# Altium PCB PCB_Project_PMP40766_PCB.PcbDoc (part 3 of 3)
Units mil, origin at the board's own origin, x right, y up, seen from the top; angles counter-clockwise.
Board outline 7480.31 x 3937.01 mil, 2 copper layers (Top Layer, Bottom Layer), stack 64.8 mil thick; 214 components, 118 nets, 518 pads, 70 vias.
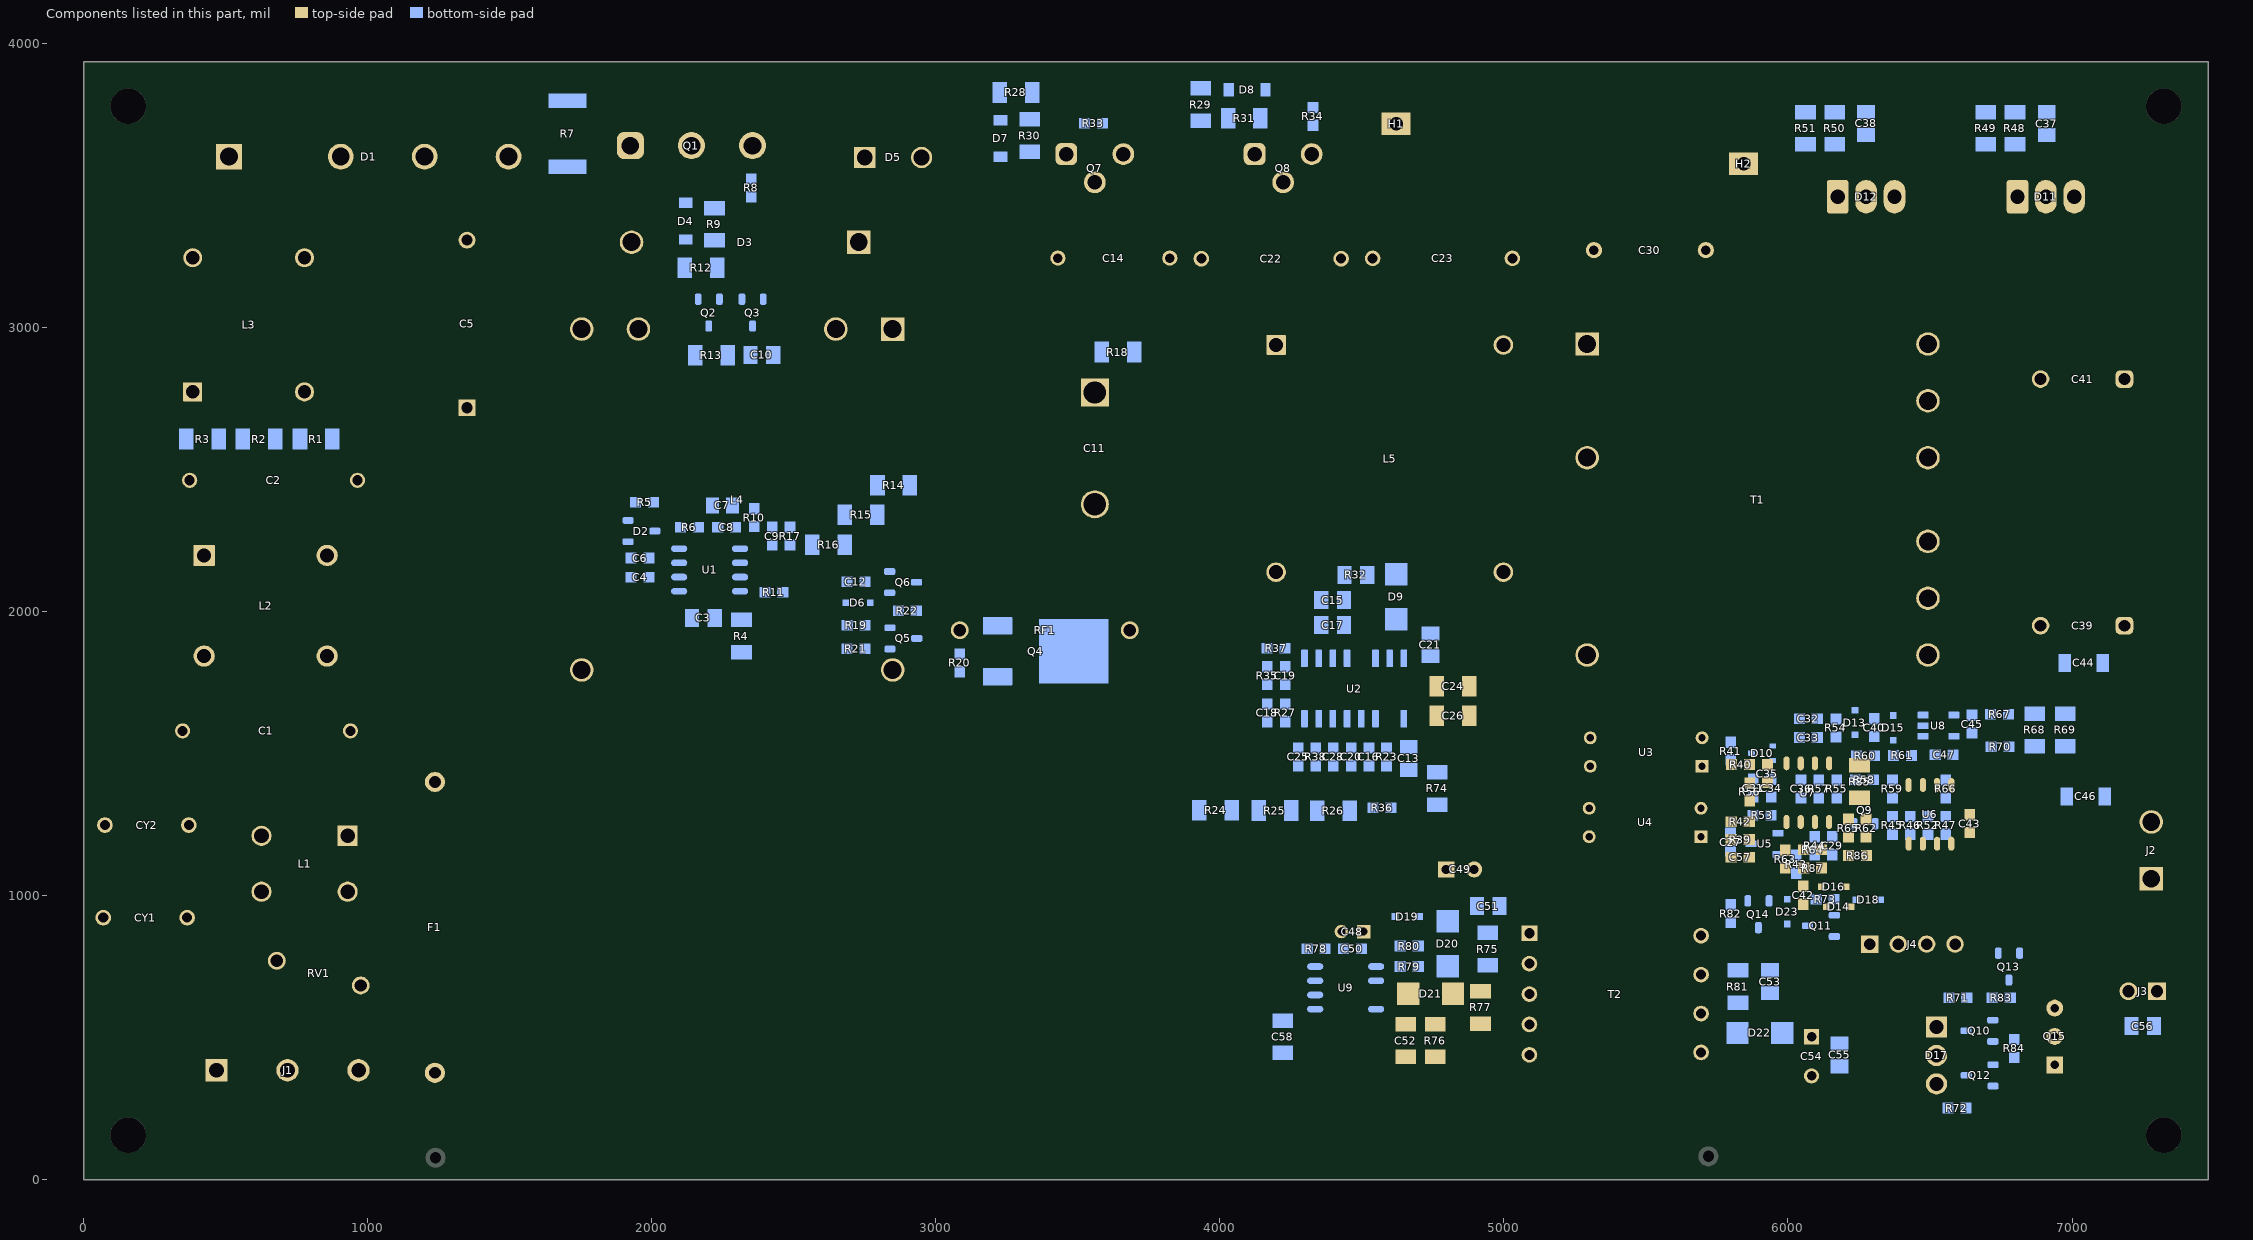
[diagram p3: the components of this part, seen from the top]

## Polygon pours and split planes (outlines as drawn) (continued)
NetC52_2 on Top Layer "Top Layer-No Net 17" (solid, pour order 136): 4623,696.26 4702,696.26 4704,694.26 4704,588.26 4717,575.26 4794,575.26 4798,571.26 4798,523.26 4795,520.26 4619,520.26 4616,523.26 4616,689.26
VBUS on Top Layer "Top Layer-No Net 18" (solid, pour order 138): 4616,471.26 5105,471.26 5118,458.26 5118,418.26 5105,405.26 4617,405.26 4610,412.26 4610,465.26
PGND on Top Layer "Top Layer-No Net 19" (solid, pour order 154): 5128,840.26 5105,817.26 5004,817.26 4944,757.26 4548,757.26 4493,702.26 4493,593.26 4447,547.26 3989,547.26 3811,725.26 3811,1409.26 4215,1813.26 4441,1813.26 4467,1787.26 4467,1767.26 4279,1579.26 4279,1542.26 4297.26,1524 4473.26,1524 4512,1485.26 4512,1337.26 4528,1321.26 4572,1321.26 4591,1340.26 4591,1450.26 4613,1472.26 4675,1472.26 4726,1421.26 4995,1421.26 5128,1288.26 5128,860.26
NetC42_2 on Top Layer "Top Layer-No Net 22" (solid, pour order 206): 6036,947 6031,952 6031,990 6035,994 6083,994 6089,1000 6089,1061 6094,1066 6139,1066 6144,1061 6144,985 6154,975 6154,952 6149,947
SGND on Bottom Layer "Bottom Layer-No Net 58" (solid, remove dead copper, pour order 214): 5753.65,1663.98 6696.65,1663.98 6800.65,1559.98 6800.65,1058.98 6921.65,937.98 7338.65,937.98 7449.65,826.98 7449.65,550.98 7450.65,549.98 7450.65,404.98 7079.39,33.72 5698.65,33.72 5665.65,66.72 5665.65,1572.72
NetF1_1 on Bottom Layer "Top Layer-No Net 1" (solid, remove dead copper, pour order 194): 858.5,932.5 913.5,877.5 913.5,620.5 946.5,587.5 1037.5,587.5 1068.5,618.5 1068.5,826.5 1161.5,919.5 1293.5,1051.5 1293.5,1411.5 1264,1441 1174,1441 1142.5,1409.5 1142.5,1144.24 1067.5,1069.24 898.5,1069.24 858.5,1029.24
"N Wire" on Bottom Layer "Top Layer-No Net 2" (solid, pour order 192): 673,321 645,349 645,605.26 539,711.26 539,1001.26 595.74,1058 683,1058 724,1017 724,899.26 802,821.26 802,349 774,321
EARTH on Bottom Layer "Bottom Layer-No Net 4" (solid, pour order 188): 22,1330.26 116,1330.26 133,1313.26 133,650 331.74,451.26 485.74,451.26 510,427 510,228 610,128 1268,128 1297,99 1297,37 1276,16 469,16 362,123 362,233 244,351 104.26,351 4,451.26 4,1312.26
12VS on Bottom Layer "Bottom Layer-No Net 57" (solid, pour order 182): 5772,927.26 5885,927.26 5941,871.26 6049,871.26 6110,810.26 6110,577.26 6004,683.26 6004,764.26 5975,793.26 5783,793.26 5748,828.26 5748,903.26
NetD7_1 on Bottom Layer "Bottom Layer-No Net 56" (solid, pour order 180): 3255,3869.26 3208,3869.26 3200,3861.26 3200,3709.26 3210,3699.26 3248,3699.26 3260,3711.26 3260,3864.26
PGND on Bottom Layer "Bottom Layer-No Net 55" (solid, pour order 178): 4355,3734.26 4308,3734.26 4284,3710.26 4284,3584.26 4300,3568.26 4346,3568.26 4364,3586.26 4364,3725.26
NetD8_2 on Bottom Layer "Bottom Layer-No Net 54" (solid, remove dead copper, pour order 176): 4305,3751.26 4201,3751.26 4174,3724.26 4174,3700.26 4161,3687.26 4161,3584.26 4145,3568.26 4092,3568.26 4076,3584.26 4076,3853.26 4095,3872.26 4330,3872.26 4352,3850.26 4352,3756.26 4347,3751.26
NetD8_1 on Bottom Layer "Bottom Layer-No Net 53" (solid, remove dead copper, pour order 174): 3897,3873.26 3891,3867.26 3891,3811.26 3896,3806.26 4048,3806.26 4057,3815.26 4057,3866.26 4050,3873.26
12VS on Bottom Layer "Bottom Layer-No Net 51" (solid, pour order 170): 5905,685.26 6009,685.26 6162,532.26 6208,532.26 6229,511.26 6229,459.26 6217,447.26 5941.7,447.26 5901,487.96 5901,681.26
NetC53_2 on Bottom Layer "Bottom Layer-No Net 50" (solid, pour order 168): 5788,770.26 5965,770.26 5974,761.26 5974,710.26 5969,705.26 5789,705.26 5783,711.26 5783,765.26
NetD22_2 on Bottom Layer "Bottom Layer-No Net 49" (solid, remove dead copper, pour order 166): 5669,624.26 5747,624.26 5807,684.26 5855,684.26 5872,667.26 5872,482.26 5858,468.26 5784,468.26 5765,487.26 5765,520.26 5739,546.26 5669,546.26 5657,558.26 5657,612.26
10V_A on Bottom Layer "Bottom Layer-No Net 48" (solid, remove dead copper, pour order 164): 5912,972.26 5891,993.59 5891,1021 5901,1031 5915,1031 5969,977 5969,969 5975.74,962.26 6044,962.26 6070,988.26 6070,1007.26 6074,1011.26 6115,1011.26 6120,1006.26 6120,935.26 6092,907.26 6092,885.26 6086,879.26 6053,879.26 6044,888.26 6044,906.26 6025,925.26 5959,925.26
NetD18_1 on Bottom Layer "Bottom Layer-No Net 47" (solid, remove dead copper, pour order 162): 6147,1013.26 6246,1013.26 6253,1006.26 6253,930.26 6240,917.26 6145,917.26 6136,926.26 6136,1002.26
NetC48_1 on Bottom Layer "Bottom Layer-No Net 37" (solid, pour order 126): 4479,899.26 4520,940.26 4630,940.26 4634,936.26 4634,910.26 4617,893.26 4578,893.26 4553,868.26 4553,810.26 4538,795.26 4481,795.26 4479,797.26
PGND on Bottom Layer "Bottom Layer-No Net 36" (solid, pour order 124): 4202.26,721.26 4183,702 4183,538 4188,533 4346,533 4401,588 4401,630 4457,686 4457,897.26 4443,911.26 4392,911.26 4350,869.26 4350,796.26 4376,770.26 4376,737.26 4360,721.26
NetR77_1 on Bottom Layer "Bottom Layer-No Net 35" (solid, pour order 122): 4976,621.26 5042,687.26 5105,687.26 5119,673.26 5119,630.26 5109,620.26 5068,620.26 4993,545.26 4522,545.26 4506,561.26 4506,609.26 4518,621.26
PGND on Bottom Layer "Bottom Layer-No Net 34" (solid, pour order 120): 2220,2508.26 2473,2508.26 2532,2449.26 2532,2303.26 2505,2276.26 2404,2276.26 2395,2285.26 2395,2411.26 2377,2429.26 2247,2429.26 2237,2419.26 2237,2337.26 2256,2318.26 2256,2152.26 2189,2085.26 2189,2030.26 2177,2018.26 2177,1956.26 2159,1938.26 1956,1938.26 1819,2075.26 1819,2332.26 1835,2348.26 1944,2348.26 1955,2337.26 1955,2097.26 1968,2084.26 2123,2084.26 2143,2104.26 2143,2431.26
NetD7_2 on Bottom Layer "Bottom Layer-No Net 22" (solid, pour order 116): 3215.5,3650.26 3422,3650.26 3480.5,3708.76 3480.5,3736.26 3483.5,3739.26 3545.5,3739.26 3548.5,3736.26 3548.5,3702.26 3542.5,3696.26 3532,3696.26 3498.5,3662.76 3498.5,3584.26 3481.5,3567.26 3213,3567.26 3201,3579.26 3201,3635.76
PGND on Bottom Layer "Bottom Layer-No Net 33" (solid, pour order 114): 2394,2877.26 2394,2954.26 2383,2965.26 2346,2965.26 2334,2977.26 2334,3032.26 2346,3044.26 2412,3044.26 2428,3060.26 2428,3499.26 2450,3521.26 2487,3521.26 2509,3499.26 2509,2882.26 2490,2863.26 2408,2863.26
NetL5_14 on Bottom Layer "Bottom Layer-No Net 32" (solid, pour order 110): 4949,3013.26 5323,3013.26 5343,2993.26 5343,2878.26 5326,2861.26 4950,2861.26 4930,2881.26 4930,2994.26
NetC22_2 on Bottom Layer "Bottom Layer-No Net 31" (solid, pour order 108): 4362,3187.26 4402,3147.26 4430,3147.26 4470,3107.26 4471.5,2854.76 4873,2453.26 5312,2453.26 5342,2483.26 5342,2678.26 5244,2776.26 4927,2776.26 4745,2958.26 4700,3003.26 4700,3203.26 4626,3277.26 4384,3277.26 4362,3255.26
NetQ4_1 on Bottom Layer "Bottom Layer-No Net 30" (solid, pour order 106): 2915,1921.26 2954,1921.26 2962,1913.26 2962,1823.26 2975,1810.26 3268,1810.26 3277,1801.26 3277,1741.26 3269,1733.26 2946,1733.26 2906,1773.26 2906,1912.26
NetR14_1 on Bottom Layer "Bottom Layer-No Net 29" (solid, pour order 104): 2771,2488.26 2817,2488.26 2824,2481.26 2824,2302.26 2819,2297.26 2770,2297.26 2765,2302.26 2765,2482.26
NetR15_1 on Bottom Layer "Bottom Layer-No Net 29" (solid, pour order 102): 2656,2384.26 2702,2384.26 2709,2377.26 2709,2198.26 2704,2193.26 2655,2193.26 2650,2198.26 2650,2378.26
VCC_PFC on Bottom Layer "Bottom Layer-No Net 28" (solid, pour order 100): 2245,2942.26 2367,2942.26 2376,2933.26 2376,2867.26 2367,2858.26 2248,2858.26 2236,2870.26 2236,2933.26
NetC9_1 on Bottom Layer "Bottom Layer-No Net 27" (solid, remove dead copper, pour order 98): 2279,2185.26 2367,2185.26 2395,2213.26 2395,2249.26 2404,2258.26 2521,2258.26 2539,2276.26 2594,2276.26 2598,2272.26 2598,2179.26 2578,2159.26 2577,2160.26 2279,2160.26 2273,2166.26 2273,2179.26
NetC8_1 on Bottom Layer "Bottom Layer-No Net 26" (solid, pour order 96): 2275,2319.26 2379,2319.26 2382,2316.26 2382,2280.26 2367,2265.26 2354,2265.26 2343,2254.26 2343,2214.26 2338,2209.26 2282,2209.26 2273,2218.26 2273,2317.26
NetC7_1 on Bottom Layer "Bottom Layer-No Net 25" (solid, pour order 94): 2264,2410.26 2372,2410.26 2382,2400.26 2382,2343.26 2376,2337.26 2265,2337.26 2260,2342.26 2260,2406.26
NetR6_2 on Bottom Layer "Bottom Layer-No Net 24" (solid, pour order 92): 2082,2320.26 2077,2315.26 2077,2245.26 2067,2235.26 2067,2214.26 2071,2210.26 2121,2210.26 2125,2214.26 2125,2315.26 2120,2320.26
HS on Bottom Layer "Bottom Layer-No Net 23" (solid, pour order 90): 3569,3739.26 3670,3739.26 3700,3709.26 3700,3581.26 3682,3563.26 3640,3563.26 3622,3581.26 3622,3683.26 3609,3696.26 3571,3696.26 3565,3702.26 3565,3735.26
NetQ2_3 on Bottom Layer "Bottom Layer-No Net 21" (solid, remove dead copper, pour order 86): 2151,3028.26 2126,3003.26 2126,2866.26 2131,2861.26 2175,2861.26 2179,2865.26 2179,2952.26 2214,2987.26 2214,3023.26 2209,3028.26
NetQ2_2 on Bottom Layer "Bottom Layer-No Net 20" (solid, pour order 84): 2183,3335.26 2259,3335.26 2263,3331.26 2263,3182.26 2276,3169.26 2400,3169.26 2419,3150.26 2419,3083.26 2411,3075.26 2379,3075.26 2369,3085.26 2369,3124.26 2354,3139.26 2277,3139.26 2263,3125.26 2263,3085.26 2253,3075.26 2227,3075.26 2214,3088.26 2214,3152.26 2179,3187.26 2179,3331.26
NetD4_1 on Bottom Layer "Bottom Layer-No Net 19" (solid, pour order 82): 2094,3335.26 2140,3335.26 2144,3331.26 2144,3175.26 2140,3171.26 2093,3171.26 2090,3174.26 2090,3331.26
VBUS on Bottom Layer "Bottom Layer-No Net 18" (solid, pour order 78): 3581.26,3550 3543,3550 3519,3526 3519,3403.26 3659,3263.26 3659,2879.26 3678,2860.26 3777,2860.26 3831,2914.26 3831,3113.26 3886,3168.26 4002,3168.26 4039,3205.26 4039,3269.26 4020,3288.26 3843,3288.26
NetD4_2 on Bottom Layer "Bottom Layer-No Net 17" (solid, remove dead copper, pour order 76): 1886,3697.26 1966,3697.26 1982,3681.26 1982,3546.26 2065,3463.26 2309,3463.26 2328,3482.26 2380,3482.26 2387,3475.26 2387,3417.26 2361,3391.26 2030,3391.26 1870,3551.26 1870,3681.26
NetC11_1 on Bottom Layer "Bottom Layer-No Net 16" (solid, pour order 74): 3330,2744.26 3330,2696.26 3340,2686.26 3595,2686.26 3629,2720.26 3629,2944.26 3597,2976.26 3364,2976.26 3029,3311.26 2889,3311.26 2887,3313.26 2826,3374.26 2826,3643.26 2803,3666.26 2674,3666.26 2648,3640.26 2648,3190.26 2728,3110.26 2964,3110.26
PGND on Bottom Layer "Bottom Layer-No Net 15" (solid, pour order 64): 1661,3926.26 2397,3926.26 2509,3814.26 2509,3499.26 2313,3499.26 2287,3525.26 2287,3705.26 2237,3755.26 1642,3755.26 1610,3787.26 1610,3875.26
NetC5_2 on Bottom Layer "Bottom Layer-No Net 14" (solid, remove dead copper, pour order 62): 1760,3495.26 1694,3495.26 1640,3441.26 1640,3375.26 1503,3238.26 1351,3238.26 1319,3270.26 1319,3320.26 1428,3429.26 1428,3648.26 1465,3685.26 1738,3685.26 1776,3647.26 1776,3511.26
NetD1_2 on Bottom Layer "Bottom Layer-No Net 13" (solid, pour order 60): 325,3299.26 465,3439.26 583,3439.26 700,3556.26 700,3642.26 744,3686.26 943,3686.26 987,3642.26 987,3546.26 872,3431.26 751,3431.26 445,3125.26 357,3125.26 356,3124.26 323,3124.26 271,3176.26 271,3249.26 322,3300.26
NetD1_3 on Bottom Layer "Bottom Layer-No Net 12" (solid, remove dead copper, pour order 58): 920,3327.26 1111,3518.26 1111,3642.26 1156,3687.26 1280,3687.26 1316,3651.26 1316,3457.26 984,3125.26 764,3125.26 728,3161.26 728,3195.26 728,3259.26 796,3327.26
NetC11_2 on Bottom Layer "Bottom Layer-No Net 11" (solid, remove dead copper, pour order 56): 3519,2445.26 3347,2273.26 3347,1764.26 3376,1735.26 3606,1735.26 3728,1857.26 3728,2373.26 3656,2445.26
NetD11_1 on Bottom Layer "Bottom Layer-No Net 8" (solid, remove dead copper, pour order 54): 6850,3527.26 6840,3537.26 6840,3541.26 6840,3670.26 6832,3678.26 6661,3678.26 6652,3669.26 6652,3616.26 6758,3510.26 6758,3412.26 6774,3396.26 6837,3396.26 6850,3409.26
NetC37_2 on Bottom Layer "Bottom Layer-No Net 9" (solid, remove dead copper, pour order 52): 6656,3784.26 6664,3792.26 6941,3792.26 6949,3784.26 6949,3733.26 6943,3727.26 6662,3727.26 6656,3733.26
VOUT on Bottom Layer "Bottom Layer-No Net 10" (solid, remove dead copper, pour order 50): 6873,3704.76 6945,3704.76 6950,3699.76 6950,3508.76 6868,3508.76 6868,3699.76
VOUT on Bottom Layer "Bottom Layer-No Net 10" (solid, remove dead copper, pour order 48): 6239,3705.26 6311,3705.26 6316,3700.26 6316,3509.26 6234,3509.26 6234,3700.26
NetC38_2 on Bottom Layer "Bottom Layer-No Net 9" (solid, remove dead copper, pour order 46): 6018,3785.26 6026,3793.26 6303,3793.26 6311,3785.26 6311,3734.26 6305,3728.26 6024,3728.26 6018,3734.26
NetD12_1 on Bottom Layer "Bottom Layer-No Net 8" (solid, remove dead copper, pour order 44): 6216,3526.26 6206,3536.26 6206,3540.26 6206,3669.26 6198,3677.26 6027,3677.26 6018,3668.26 6018,3615.26 6124,3509.26 6124,3411.26 6140,3395.26 6203,3395.26 6216,3408.26
SGND on Bottom Layer "Bottom Layer-No Net 7" (solid, pour order 42): 6574,2849.26 6574,2712.26 6524,2662.26 6523,2663.26 6460,2663.26 6085,3038.26 6085,3482.26 5912,3655.26 5705,3655.26 5675,3625.26 5675,1751.26 5750,1676.26 6820,1676.26 6830,1665.26 6830,1618.26 6837,1611.26 7010,1611.26 7019,1620.26 7019,2800.26 6901,2918.26 6643,2918.26
NetC46_2 on Bottom Layer "Bottom Layer-No Net 6" (solid, pour order 40): 7350.74,1131.26 7187,1131.26 7019,1299.26 7019,1547.26 7012,1554.26 6834,1554.26 6830,1550.26 6830,1073.26 6953.26,950 7342,950 7375,983 7375,1107
VOUT on Bottom Layer "Bottom Layer-No Net 5" (solid, remove dead copper, pour order 38): 6245,3530.26 6303,3530.26 6316,3517.26 6316,3385.26 6333,3368.26 6843,3368.26 6868,3393.26 6868,3516.26 6882,3530.26 6934,3530.26 6950,3514.26 6950,3398.26 6980,3368.26 7302,3368.26 7440,3230.26 7440,1266.26 7371,1197.26 7213,1197.26 7078,1332.26 7078,1798.26 7078,2848.26 6876,3050.26 6290,3050.26 6234,3106.26 6234,3519.26
NetC2_1 on Bottom Layer "Bottom Layer-No Net 3" (solid, pour order 28): 467,2833.26 483,2817.26 483,2749.26 463,2729.26 431,2729.26 388,2686.26 388,2531.26 491,2428.26 491,2129.26 450,2088.26 325,2088.26 283,2130.26 283,2810.26 306,2833.26
NetC2_2 on Bottom Layer "Bottom Layer-No Net 2" (solid, pour order 26): 880,2832.26 1001,2711.26 1001,2145.26 944,2088.26 818,2088.26 780,2126.26 780,2398.26 851,2469.26 851,2688.26 809,2730.26 732,2730.26 710,2752.26 710,2813.26 729,2832.26
NetR2_1 on Bottom Layer "Bottom Layer-No Net 1" (solid, pour order 24): 451,2647.26 584,2647.26 587,2644.26 587,2572.26 582,2567.26 450,2567.26 448,2569.26 448,2644.26
NetR1_1 on Bottom Layer "Bottom Layer-No Net 1" (solid, pour order 22): 652,2647.26 785,2647.26 788,2644.26 788,2572.26 783,2567.26 651,2567.26 649,2569.26 649,2644.26
NetC1_1 on Bottom Layer "Bottom Layer-No Net" (solid, pour order 20): 947,1893.26 809,1893.26 780,1864.26 780,1487.26 717,1424.26 462,1424.26 326,1288.26 326,1233.26 355,1204.26 410,1204.26 533,1327.26 788,1327.26 838,1277.26 838,1184 887,1135 993,1135 1044,1186 1044,1630.26 974,1700.26 974,1866.26
NetD20_2 on Bottom Layer "Bottom Layer-No Net 38" (solid, pour order 128): 4762.5,793.26 4740.5,771.26 4681,771.26 4677,767.26 4677,720.76 4684,713.76 4972.5,713.76 4991,732.26 5111,732.26 5119,740.26 5119,785.26 5111,793.26
NetC51_1 on Bottom Layer "Bottom Layer-No Net 39" (solid, pour order 130): 4907,897.26 4929,897.26 4959,927.26 4959,995.26 4963,999.26 5009,999.26 5011,997.26 5011,926.26 4979,894.26 4979,844.26 4978,843.26 4911,843.26 4907,847.26
PGND on Bottom Layer "Bottom Layer-No Net 40" (solid, pour order 140): 3261.26,1833.26 3279,1851 3279,2272 3193,2358 2871.74,2358 2855,2341.26 2855,2292.26 2835,2272.26 2755,2272.26 2728,2245.26 2728,2087.26 2735,2080.26 2806,2080.26 2864,2138.26 2961,2138.26 2981,2118.26 2981,1845.26 2993,1833.26
NetR24_1 on Bottom Layer "Bottom Layer-No Net 41" (solid, pour order 142): 4152,1350.26 4166,1336.26 4166,1262.26 4155,1251.26 4022,1251.26 4009,1264.26 4009,1337.26 4022,1350.26
NetR25_1 on Bottom Layer "Bottom Layer-No Net 41" (solid, pour order 144): 4361,1350.26 4375,1336.26 4375,1262.26 4364,1251.26 4231,1251.26 4218,1264.26 4218,1337.26 4231,1350.26
BLK on Bottom Layer "Bottom Layer-No Net 41" (solid, pour order 146): 4447.5,1369.26 4540,1369.26 4561,1348.26 4561,1273.26 4545,1257.26 4434.5,1257.26 4421.5,1270.26 4421.5,1343.26
NetC49_1 on Bottom Layer "Bottom Layer-No Net 42" (solid, pour order 148): 4828,1026.26 4853,1001.26 4927,1001.26 4931,997.26 4931,929.26 4923,921.26 4851,921.26 4843,913.26 4843,871.26 4839,867.26 4763,867.26 4758,872.26 4758,900.26 4745,913.26 4690,913.26 4686,917.26 4686,950.26 4719,983.26 4719,1279.26 4719,1338.26 4728,1347.26 4808,1347.26 4828,1327.26
PGND on Bottom Layer "Bottom Layer-No Net 43" (solid, pour order 150): 5089,1346.26 5125,1310.26 5125,829.26 5098,802.26 4115,802.26 4018,899.26 4018,1193.26 4043,1218.26 4568,1218.26 4696,1346.26
PGND on Bottom Layer "Bottom Layer-No Net 44" (solid, remove dead copper, pour order 152): 5324,1294.26 5324,1327.26 5262,1389.26 5262,1472.26 5331,1541.26 5331,1596.26 5197.26,1730 4504.26,1730 4421,1813.26 4421,2179.26 4254,2346.26 4042,2346.26 4019,2323.26 4019,1477.26 4094,1402.26 5139,1402.26 5260,1281.26 5311,1281.26
HS on Bottom Layer "Bottom Layer-No Net 59" (solid, pour order 200): 4639,1888 4659,1888 4677,1870 4774,1870 4777,1867 4777,1808 4773,1804 4639,1804 4635,1808 4635,1884
HB on Bottom Layer "Bottom Layer-No Net 60" (solid, remove dead copper, pour order 202): 4710,2015 4580,2015 4574,2009 4574,1941 4585,1930 4673,1930 4706,1897 4772,1897 4775,1900 4775,1950
PGND on Bottom Layer "Bottom Layer-No Net 61" (solid, pour order 204): 2394,2882.26 2394,2860 2143,2609 2143,2431.26 2525.26,2431.26 2532,2438 2532,2859.26 2509,2882.26
NetC56_2 on Bottom Layer "Bottom Layer-No Net 45" (solid, remove dead copper, pour order 158): 6941.26,700.26 6898,657 6898,591 6923,566 6924,567 7108,567 7170,506.26 7232,506.26 7237,511.26 7237,685.26 7222,700.26
NetQ13_3 on Bottom Layer "Bottom Layer-No Net 46" (solid, pour order 208): 6770,723 6792,723 6822,693 6822,562 6848,536 6960,536 6976,520 6976,481 6962,467 6780,467 6760,487 6760,713
12VS on Bottom Layer "Bottom Layer-No Net 52" (solid, pour order 210): 6208,532.26 6288.74,532.26 6453,368 6453,291 6527,217 6964,217 7258,511 7258,689 7272,703 7352,703 7370,685 7370,429 7041,100 6502,100 6317,285 6317,354 6283,388 6223.74,447.26 6208,447.26 6208,511.26

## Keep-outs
Keep-Out Layer:
  text ".Layer_Name" at 577,-937.23 h60

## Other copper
Top Layer:
  text ".Layer_Name" at 577,-937.23 h60
Bottom Layer:
  pour cut-out: 6447,2122.26 6546,2122.26 6571,2097.26 6571,1807.26 6538,1774.26 6442,1774.26 6418,1798.26 6418,2094.26 6445,2121.26
  text ".Layer_Name" at 577,-937.23 h60

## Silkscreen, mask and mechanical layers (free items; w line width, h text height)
Top Overlay:
  circle w5: c7322.83,3779.53 r118.11
  circle w5: c7322.83,157.48 r118.11
  circle w5: c157.48,157.48 r118.11
  circle w5: c157.48,3779.53 r118.11
  text "VBAT+" at 7151,1412.26 h60
  text "PMP40766" at 1755,1062 h60
  text "Rev.E2" at 1757,966 h60
  text "VBAT-" at 7151,864.26 h60
  text "N" at 548,612 h60
  text "L" at 1375,522 h60
  text "+" at 7347,504.26 h40
  text "-" at 7140,501.26 h40
  text "EARTH" at 20,495 h60
  text ".Layer_Name" at 577,-937.23 h40
Bottom Overlay:
  text ".Layer_Name" at 577,-937.23 h40
Top Paste:
  text ".Layer_Name" at 577,-937.23 h60
Bottom Paste:
  text ".Layer_Name" at 577,-937.23 h60
Top Solder:
  text ".Layer_Name" at 577,-937.23 h60
  text ".Layer_Name" at 577,-937.23 h60
Bottom Solder:
  lines w60: 432,3263.26 481,3263.26 816,3598.26 ; 877,3220.26 939,3220.26 1197,3478.26 1197,3502.26 ; 1832,3814.26 2396,3814.26 ; 6280,3138 7043,3138 7244,2937 ; 6288,3281 7127,3281 7129,3281 7333,3077 ; 6754,2047 6754,2738 ; 6880,1181 7045,1016 ; 6886,2048 6886,2739 ; 6949,1273 7149,1073 ; 7212,2067 7212,2736 ; 7213,1381 7213,1843 ; 7342,1387 7342,2738
  text ".Layer_Name" at 577,-937.23 h60
Drill Guide:
  text ".Layer_Name" at 577,-937.23 h60
M1 Board Outline:
  the board outline again, w10
  text ".Layer_Name" at 577,-937.23 h60
M2 Board Dimensions:
  rectangle: 0,-353.74 125,-228.74
  rectangle: 125,-478.74 500,-353.74
  lines w7: 0,-353.74 1000,-353.74 ; 125,-478.74 125,-228.74 ; 250,-478.74 250,-228.74 ; 500,-478.74 500,-228.74 ; 750,-478.74 750,-228.74 ; 0,-478.74 1000,-478.74 1000,-228.74 0,-228.74 0,-478.74
  text ".Layer_Name" at 577,-937.23 h60
M3 3D STEP Top:
  text ".Layer_Name" at 577,-937.23 h60
M4 3D STEP Bottom:
  text ".Layer_Name" at 577,-937.23 h60
M5 Assembly Top:
  lines w10: -292,-1008.91 6308,-1008.91 ; -292,-805.57 6310,-805.57 ; -292,-602.24 -292,-1212.24 3713,-1212.24 6310,-1212.24 6310,-602.24 -291.5,-602.24 -291.5,-1212.24 1284,-1212.24 ; 2173,-1212.24 2173,-602.24 ; 3440,-805.57 3440,-602.24 ; 4280,-805.57 4280,-602.24 ; 4902,-1218.74 4902,-1015.91
  text "COMPONENTS MARKED 'DNP' SHOULD NOT BE POPULATED." at 1153.5,-397.24 h60
  text "ASSEMBLY VARIANT:" at 1153,-512.74 h60
  text ".VariantName" at 2189,-512.74 h60
  text "PCB VIEWED FROM TOP SIDE" at -228.5,-734.41 h60
  text "BOARD #:" at 2248,-734.41 h60
  text ".PRJ_Number" at 2793.5,-734.41 h60
  text "REV:" at 3638,-734.41 h60
  text ".PCB_Rev" at 3929.5,-734.41 h60
  text "SVN REV:" at 4476,-734.41 h60
  text ".VersionControl_RevNumber" at 4982,-734.41 h60
  text "TID #:" at 2248,-937.74 h60
  text ".TID" at 2793.5,-937.74 h60
  text "PLOT NAME =" at -228.5,-1143.08 h60
  text ".plot_File_Name" at 577,-1143.08 h60
  text "GENERATED    :" at 2250,-1143.08 h60
  text ".Print_Date" at 3119.5,-1143.08 h60
  text ".Print_Time" at 3848.5,-1143.08 h60
  text "TEXAS INSTRUMENTS" at 5113,-1143.08 h60
M6 Assembly Bottom:
  lines w10: -292.5,-806.07 6309.5,-806.07 ; -290.5,-1009.41 6309.5,-1009.41 ; 1115.5,-1219.24 1115.5,-1016.41 ; 1737.5,-806.07 1737.5,-602.74 ; 2577.5,-806.07 2577.5,-602.74 ; 3844.5,-1212.74 3844.5,-602.74 ; 4733.5,-1212.74 6309,-1212.74 6309,-602.74 -292.5,-602.74 -292.5,-1212.74 2304.5,-1212.74 6309.5,-1212.74 6309.5,-602.74
  text "COMPONENTS MARKED 'DNP' SHOULD NOT BE POPULATED." at 6102,-396.74 h60
  text ".VariantName" at 5058,-512.74 h60
  text "ASSEMBLY VARIANT:" at 6097,-512.74 h60
  text ".VersionControl_RevNumber" at 1035.5,-734.91 h60
  text "SVN REV:" at 1541.5,-734.91 h60
  text ".PCB_Rev" at 2088,-734.91 h60
  text "REV:" at 2379.5,-734.91 h60
  text ".PRJ_Number" at 3224,-734.91 h60
  text "BOARD #:" at 3769.5,-734.91 h60
  text "PCB VIEWED FROM BOTTOM SIDE" at 6246,-734.91 h60
  text ".TID" at 3224,-938.24 h60
  text "TID #:" at 3769.5,-938.24 h60
  text "TEXAS INSTRUMENTS" at 904.5,-1143.58 h60
  text ".Print_Time" at 2169,-1143.58 h60
  text ".Print_Date" at 2898,-1143.58 h60
  text "GENERATED    :" at 3767.5,-1143.58 h60
  text ".plot_File_Name" at 5440.5,-1143.58 h60
  text "PLOT NAME =" at 6246,-1143.58 h60
M9 Title Sheet:
  drawing of 57 lines, arcs and shapes, not listed
  text "1" at 739.84,7957.76 h70
  text "2" at 3235.5,7957.76 h70
  text "3" at 5724.84,7957.76 h70
  text "4" at 8231.51,7957.76 h70
  text "5" at 10730.5,7957.76 h70
  text "6" at 13235.5,7957.76 h70
  text "A" at -416.5,6814.76 h70
  text "A" at 14383.5,6814.76 h70
  text "B" at -416.5,4434.76 h70
  text "B" at 14383.5,4434.76 h70
  text "C" at -416.5,2059.76 h70
  text "C" at 14383.5,2059.76 h70
  text "PROJECT TITLE:" at 11343.5,198.76 h45
  text ".PRJ_Title" at 11393.5,65.43 h70
  text "DESIGNED FOR:" at 11343.5,-102.24 h45
  text ".PRJ_Customer" at 11393.5,-242.24 h70
  text "D" at -416.5,-310.24 h70
  text "D" at 14383.5,-310.24 h70
  text "FILE NAME:" at 11343.5,-402.24 h45
  text ".PCB_File_Name_No_Path" at 11393.5,-522.24 h70
  text "Texas Instruments (TI) and/or its licensors do not warrant the accuracy or completeness of this specification" at 6374,-684.08 h45
  text "ENGINEER:" at 11343.5,-692.24 h45
  text "LAYOUT BY:" at 12848.5,-692.24 h45
  text "or any information contained therein. TI and/or its licensors do not warrant that this design will meet" at 6329.01,-796.74 h45
  text ".PRJ_Engineer" at 11393.5,-847.23 h70
  text ".PCB_Layout" at 12899,-847.23 h70
  text "the specifications, will be suitable for your application or fit for any particular purpose, or will operate in" at 6329.01,-909.41 h45
  text ".Layer_Name" at 577,-937.23 h60
  text "ALTIUM DESIGNER VERSION:" at 12848.5,-1002.24 h45
  text "an implementation. TI and/or its licensors do not warrant that the design is production worthy. You should" at 6329.01,-1022.07 h45
  text "completely validate and test your design implementation to confirm the system functionality for your application." at 6374,-1134.74 h45
  text ".print_Scale" at 11393.5,-1135.57 h70
  text ".Application_BuildNumber" at 12899,-1135.57 h70
  text "1" at 739.84,-1342.24 h70
  text "2" at 3235.5,-1342.24 h70
  text "3" at 5724.84,-1342.24 h70
  text "4" at 8231.51,-1342.24 h70
  text "5" at 10730.5,-1342.24 h70
  text "6" at 13235.5,-1342.24 h70
M10 Fab Notes:
  drawing of 189 lines, arcs and shapes, not listed
  text "DESIGN INFORMATION" at 12382.02,6277.43 h60
  text "MIN. TRACK WIDTH:" at 11737.46,6145.31 h60
  text "8" at 12833.7,6145.31 h60
  text "MIL" at 12988.46,6145.31 h60
  text "MIN. CLEARANCE:" at 11737.46,6021.18 h60
  text "0.2" at 12773.7,6021.18 h60
  text "mm" at 12988.46,6021.18 h60
  text "MIN. VIA PAD SIZE:" at 11737.46,5897.06 h60
  text "24" at 12803.71,5897.06 h60
  text "MIL" at 12988.46,5897.06 h60
  text "0.05mm (2MIL)" at 12432.46,5767.16 h60
  text "MINIMUM ANNULAR RING" at 11408.23,5758.93 h60
  text "EXTERNAL" at 13140.46,5758.93 h60
  text "PER" at 11608.23,5648.81 h60
  text "IPC-D-275 CLASS 2 LEVEL C" at 11828.23,5648.8 h60
  text "MIL, HOLES" at 13316.46,5548.33 h60
  text "+/-" at 12924,5539.74 h60
  text "+/-" at 13778,5539.74 h60
  text "REGISTRATION TOLERANCES:" at 11408.23,5538.68 h60
  text "METAL" at 12608,5538.68 h60
  text "5" at 13184.2,5538.68 h60
  text "3" at 14017.2,5538.68 h60
  text "MIL" at 14133.46,5538.68 h60
  text "HOLE SIZE TOLERANCE (UNLESS OTHERWISE SPECIFIED):" at 11408.23,5440.36 h60
  text "+/-" at 13778,5437.49 h60
  text "3" at 14017.2,5436.43 h60
  text "MIL" at 14133.46,5436.43 h60
  text "MATERIAL:" at 11333.46,5298.78 h60
  text "FR-4 High Tg" at 12319.9,5170.26 h60
  text "X" at 12175.46,5162.27 h60
  text "FR-408" at 11754.46,5157.75 h60
  text "OTHER" at 13242.46,5157.75 h60
  text "62 MIL (1.6mm) +/-10%" at 12074.56,5014.72 h60
  text "X" at 11954.46,5012.27 h60
  text "THICKNESS:" at 11408.23,5006.5 h60
  text "OTHER" at 13359.46,5006.5 h60
  text "TOLERANCE:" at 11408.23,4868.18 h60
  text "X" at 12256.46,4868.18 h60
  text "ANSI IPC-6012 TYPE 3 CLASS 2" at 12434.48,4868.18 h60
  text "OTHER +/-" at 12434.46,4723.99 h60
  text "BOW & TWIST:" at 11408.23,4578.8 h60
  text "X" at 12256.46,4578.8 h60
  text "ANSI IPC-6012 TYPE 3 CLASS 2" at 12434.48,4578.8 h60
  text "OTHER +/-" at 12434.46,4432.11 h60
  text "DRILLING:" at 11333.46,4301.49 h60
  text "NC_DRILL FILES" at 13094.46,4196.3 h60
  text "REFERENCE:" at 11408.23,4192.36 h60
  text "X" at 12065.46,4192.27 h60
  text "AS SHOWN" at 12243.46,4192.36 h60
  text "X" at 12966.46,4192.36 h60
  text "OTHER" at 13392.46,4050.11 h60
  text "PTH COPPER THICKNESS:" at 11407.91,4046.58 h60
  text "X" at 12547.14,4046.58 h60
  text "20-30 um" at 12675.14,4046.58 h60
  text "BOARD FINISH:" at 11333.46,3898.99 h60
  text "SILKSCREEN:" at 11488.68,3788.86 h60
  text "X" at 12446.46,3788.86 h60
  text "TOP" at 12563.46,3788.86 h60
  text "X" at 12956.46,3788.86 h60
  text "BOTTOM" at 13074.46,3788.86 h60
  text "SILKSCREEN COLOR:" at 11488.68,3633.67 h60
  text "X" at 12445.46,3633.67 h60
  text "WHITE" at 12563.46,3633.67 h60
  text "OTHER" at 13074.46,3633.67 h60
  text "X" at 12576.46,3490.22 h60
  text "GREEN" at 12694.46,3490.22 h60
  text "OTHER" at 13312.46,3490.22 h60
  text "SOLDER RESIST COLOR:" at 11488.68,3483.36 h60
  text "X" at 12576.46,3335.97 h60
  text "MATTE" at 12694.46,3335.97 h60
  text "SEMI-GLOSS" at 13312,3335.33 h60
  text "IMMERSION GOLD (ENIG)" at 12394.46,3163.2 h60
  text "ENEPIG" at 13732,3155.98 h60
  text "SURFACE FINISH:" at 11333.46,3154.98 h60
  text "X" at 12216.46,3154.98 h60
  text "IMM. TIN/SILVER OR EQUIV" at 11663,3017.66 h60
  text "OTHER" at 13094.46,3013.73 h60
  text "ARRAY/PANEL:" at 11333.46,2858.35 h60
  text "CUT AND TRIM PER M1 BOARD OUTLINE" at 12394.46,2850.13 h60
  text "N.C. ROUTE" at 12394.46,2714.16 h60
  text "X" at 13082.46,2714.16 h60
  text "V. SCORE" at 13260.46,2714.16 h60
  text "CERTIFICATION:" at 11333.46,2585.03 h60
  text "MATERIALS AND WORKMANSHIP FOR ALL PCBS" at 12058.46,2585.03 h60
  text "TO MEET OR EXCEED THE REQUIREMENTS OF:" at 12058.46,2490.97 h60
  text "X" at 11695.97,2362.34 h60
  text "ANSI IPC-A-600F CLASS ->" at 11823.96,2362.34 h60
  text "X" at 13471.97,2362.34 h60
  text "2" at 13581.96,2362.34 h60
  text "1" at 13266.96,2360.84 h60
  text "3" at 13935.96,2360.84 h60
  text "X" at 12507.97,2214.65 h60
  text "RoHS" at 12635.96,2214.65 h60
  text "OTHER" at 13280.36,2214.65 h60
  text "PER ORDER" at 13677.42,2214.65 h60
  text "ALL BOARDS MUST MEET OR EXCEED UL94-V0 REQUIREMENTS." at 11361,2060.83 h60
  text "PCB MUST BEAR THE UL94V-0 UL REGISTERED MATERIAL ID NUMBER" at 11361,1944.76 h60
  text "ADDITIONAL REQUIREMENTS:" at 11333.46,1775.34 h60
  text "MICROSECTION:" at 11408.23,1668.21 h60
  text "YES" at 12313.96,1668.21 h60
  text "REQUIRED" at 13175.46,1523.88 h60
  text "BARE BOARD ELEC. TEST:" at 11408.23,1521.02 h60
  text "NONE" at 12713.96,1521.02 h60
  text "X" at 13057.46,1521.02 h60
  text "PER ORDER" at 13767.46,1521.02 h60
  text "XX MIL VIAS REQUIRE NON-CONDUCTIVE FILL AND PLANARIZE" at 11576.38,1316.08 h59
  text "XX MIL VIAS REQUIRE CONDUCTIVE FILL AND PLANARIZE" at 11584.38,1212.1 h60
  text "OUTER XX MIL TRACES REQUIRE 50 OHM SINGLE-ENDED IMPEDANCE" at 11583.39,1048.72 h58
  text "LAYER 2 & 3 (INNER LAYERS) XX MIL WIDE, XX MIL SPACE / TRACES REQUIRE 100 OHM DIFFERENTIAL IMPEDANCE" at 11575.39,813 h60
  text ".Layer_Name" at 577,-937.23 h60
M11 Gerber Information:
  lines w10: -292,-1008.91 6308,-1008.91 ; -292,-805.57 6310,-805.57 ; -292,-602.24 -292,-1212.24 3713,-1212.24 6310,-1212.24 6310,-602.24 -291.5,-602.24 -291.5,-1212.24 1284,-1212.24 ; 2173,-1212.24 2173,-602.24 ; 3440,-805.57 3440,-602.24 ; 4280,-805.57 4280,-602.24 ; 4902,-1218.74 4902,-1015.91
  text "ALL ARTWORK VIEWED FROM TOP SIDE" at -228.5,-734.41 h60
  text "BOARD #:" at 2248,-734.41 h60
  text ".PRJ_Number" at 2793.5,-734.41 h60
  text "REV:" at 3638,-734.41 h60
  text ".PCB_Rev" at 3929.5,-734.41 h60
  text "SVN REV:" at 4476,-734.41 h60
  text ".VersionControl_RevNumber" at 4982,-734.41 h60
  text "LAYER NAME =" at -228.5,-937.23 h60
  text "TID #:" at 2248,-937.74 h60
  text ".TID" at 2793.5,-937.74 h60
  text "PLOT NAME =" at -228.5,-1143.08 h60
  text ".plot_File_Name" at 577,-1143.08 h60
  text "GENERATED    :" at 2250,-1143.08 h60
  text ".Print_Date" at 3119.5,-1143.08 h60
  text ".Print_Time" at 3848.5,-1143.08 h60
  text "TEXAS INSTRUMENTS" at 5113,-1143.08 h60
M12 Stackup:
  drawing of 191 lines, arcs and shapes, not listed
  text "Layer" at 9797.84,7751.26 h60
  text "Name" at 10207.76,7751.26 h60
  text "Material" at 11137.5,7751.26 h60
  text "Thickness" at 11997.27,7751.26 h60
  text "Constant" at 12647.1,7751.26 h60
  text "Board Layer Stack" at 13216.96,7751.26 h60
  text "1" at 9797.84,7631.26 h60
  text "Top Overlay" at 10207.76,7631.26 h60
  text "2" at 9797.84,7511.26 h60
  text "Top Solder" at 10207.76,7511.26 h60
  text "Solder Resist" at 11137.5,7511.26 h60
  text "0.40mil" at 11997.27,7511.26 h60
  text "3.5" at 12647.1,7511.26 h60
  text "3" at 9797.84,7391.26 h60
  text "Top Layer" at 10207.76,7391.26 h60
  text "Copper" at 11137.5,7391.26 h60
  text "2.80mil" at 11997.27,7391.26 h60
  text "4" at 9797.84,7271.26 h60
  text "Dielectric1" at 10207.76,7271.26 h60
  text "FR-4" at 11137.5,7271.26 h60
  text "59.20mil" at 11997.27,7271.26 h60
  text "4.8" at 12647.1,7271.26 h60
  text "5" at 9797.84,7151.26 h60
  text "Bottom Layer" at 10207.76,7151.26 h60
  text "Copper" at 11137.5,7151.26 h60
  text "2.80mil" at 11997.27,7151.26 h60
  text "6" at 9797.84,7031.26 h60
  text "Bottom Solder" at 10207.76,7031.26 h60
  text "Solder Resist" at 11137.5,7031.26 h60
  text "0.40mil" at 11997.27,7031.26 h60
  text "3.5" at 12647.1,7031.26 h60
  text "7" at 9797.84,6911.26 h60
  text "Bottom Overlay" at 10207.76,6911.26 h60
  text ".Layer_Name" at 577,-937.23 h60
M13 Component Bodies Top:
  text ".Layer_Name" at 577,-937.23 h60
M14 Component Bodies Bottom:
  text ".Layer_Name" at 577,-937.23 h60
M15 Courtyards Top:
  text ".Layer_Name" at 577,-937.23 h60
M16 Courtyards Bottom:
  text ".Layer_Name" at 577,-937.23 h60
Drill Drawing:
  drawing of 184 lines, arcs and shapes, not listed
  text "Symbol" at 14282.61,7579.87 h72
  text "Quantity" at 14568.36,7579.87 h72
  text "Finished Hole Size" at 14885.54,7579.87 h72
  text "Plated" at 15507.29,7579.87 h72
  text "Hole Type" at 15751.61,7579.87 h72
  text "Drill Layer Pair" at 16111.95,7579.87 h72
  text "Hole Tolerance" at 16821.46,7579.87 h72
  text "70" at 14568.36,7480.25 h60
  text "12.00mil (0.305mm)" at 14885.54,7480.25 h60
  text "PTH" at 15507.29,7480.25 h60
  text "Round" at 15751.61,7480.25 h60
  text "Top Layer - Bottom Layer" at 16111.95,7480.25 h60
  text "E" at 14260.99,7470.25 h44.28
  text "8" at 14568.36,7380.63 h60
  text "25.59mil (0.650mm)" at 14885.54,7380.63 h60
  text "PTH" at 15507.29,7380.63 h60
  text "Round" at 15751.61,7380.63 h60
  text "Top Layer - Bottom Layer" at 16111.95,7380.63 h60
  text "1" at 14568.36,7281 h60
  text "28.00mil (0.711mm)" at 14885.54,7281 h60
  text "PTH" at 15507.29,7281 h60
  text "Round" at 15751.61,7281 h60
  text "Top Layer - Bottom Layer" at 16111.95,7281 h60
  text "1" at 14568.36,7181.38 h60
  text "28.01mil (0.712mm)" at 14885.54,7181.38 h60
  text "PTH" at 15507.29,7181.38 h60
  text "Round" at 15751.61,7181.38 h60
  text "Top Layer - Bottom Layer" at 16111.95,7181.38 h60
  text "3" at 14568.36,7081.76 h60
  text "29.53mil (0.750mm)" at 14885.54,7081.76 h60
  text "PTH" at 15507.29,7081.76 h60
  text "Round" at 15751.61,7081.76 h60
  text "Top Layer - Bottom Layer" at 16111.95,7081.76 h60
  text "2" at 14568.36,6982.14 h60
  text "31.00mil (0.787mm)" at 14885.54,6982.14 h60
  text "PTH" at 15507.29,6982.14 h60
  text "Round" at 15751.61,6982.14 h60
  text "Top Layer - Bottom Layer" at 16111.95,6982.14 h60
  text "6" at 14568.36,6882.51 h60
  text "33.47mil (0.850mm)" at 14885.54,6882.51 h60
  text "PTH" at 15507.29,6882.51 h60
  text "Round" at 15751.61,6882.51 h60
  text "Top Layer - Bottom Layer" at 16111.95,6882.51 h60
  text "21" at 14568.36,6782.89 h60
  text "35.43mil (0.900mm)" at 14885.54,6782.89 h60
  text "PTH" at 15507.29,6782.89 h60
  text "Round" at 15751.61,6782.89 h60
  text "Top Layer - Bottom Layer" at 16111.95,6782.89 h60
  text "4" at 14568.36,6683.27 h60
  text "39.37mil (1.000mm)" at 14885.54,6683.27 h60
  text "PTH" at 15507.29,6683.27 h60
  text "Round" at 15751.61,6683.27 h60
  text "Top Layer - Bottom Layer" at 16111.95,6683.27 h60
  text "D" at 14260.99,6673.28 h44.28
  text "4" at 14568.36,6583.65 h60
  text "40.16mil (1.020mm)" at 14885.54,6583.65 h60
  text "PTH" at 15507.29,6583.65 h60
  text "Round" at 15751.61,6583.65 h60
  text "Top Layer - Bottom Layer" at 16111.95,6583.65 h60
  text "I" at 14268.36,6573.65 h44.28
  text "2" at 14568.36,6484.02 h60
  text "41.00mil (1.041mm)" at 14885.54,6484.02 h60
  text "PTH" at 15507.29,6484.02 h60
  text "Round" at 15751.61,6484.02 h60
  text "Top Layer - Bottom Layer" at 16111.95,6484.02 h60
  text "C" at 14260.99,6474.03 h44.28
  text "4" at 14568.36,6384.4 h60
  text "41.34mil (1.050mm)" at 14885.54,6384.4 h60
  text "PTH" at 15507.29,6384.4 h60
  text "Round" at 15751.61,6384.4 h60
  text "Top Layer - Bottom Layer" at 16111.95,6384.4 h60
  text "G" at 14260.99,6374.41 h44.28
  text "2" at 14568.36,6284.78 h60
  text "42.91mil (1.090mm)" at 14885.54,6284.78 h60
  text "PTH" at 15507.29,6284.78 h60
  text "Round" at 15751.61,6284.78 h60
  text "Top Layer - Bottom Layer" at 16111.95,6284.78 h60
  text "4" at 14568.36,6185.16 h60
  text "43.31mil (1.100mm)" at 14885.54,6185.16 h60
  text "PTH" at 15507.29,6185.16 h60
  text "Round" at 15751.61,6185.16 h60
  text "Top Layer - Bottom Layer" at 16111.95,6185.16 h60
  text "4" at 14568.36,6085.53 h60
  text "47.24mil (1.200mm)" at 14885.54,6085.53 h60
  text "PTH" at 15507.29,6085.53 h60
  text "Round" at 15751.61,6085.53 h60
  text "Top Layer - Bottom Layer" at 16111.95,6085.53 h60
  text "11" at 14568.36,5985.91 h60
  text "49.21mil (1.250mm)" at 14885.54,5985.91 h60
  text "PTH" at 15507.29,5985.91 h60
  text "Round" at 15751.61,5985.91 h60
  text "Top Layer - Bottom Layer" at 16111.95,5985.91 h60
  text "A" at 14260.99,5975.92 h44.28
  text "6" at 14568.36,5886.29 h60
  text "50.00mil (1.270mm)" at 14885.54,5886.29 h60
  text "PTH" at 15507.29,5886.29 h60
  text "Round" at 15751.61,5886.29 h60
  text "Top Layer - Bottom Layer" at 16111.95,5886.29 h60
  text "F" at 14260.99,5876.3 h44.28
  text "13" at 14568.36,5786.67 h60
  text "51.18mil (1.300mm)" at 14885.54,5786.67 h60
  text "PTH" at 15507.29,5786.67 h60
  text "Round" at 15751.61,5786.67 h60
  text "Top Layer - Bottom Layer" at 16111.95,5786.67 h60
  text "B" at 14260.99,5776.67 h44.28
  text "2" at 14568.36,5687.04 h60
  text "55.12mil (1.400mm)" at 14885.54,5687.04 h60
  text "PTH" at 15507.29,5687.04 h60
  text "Round" at 15751.61,5687.04 h60
  text "Top Layer - Bottom Layer" at 16111.95,5687.04 h60
  text "3" at 14568.36,5587.42 h60
  text "62.00mil (1.575mm)" at 14885.54,5587.42 h60
  text "PTH" at 15507.29,5587.42 h60
  text "Round" at 15751.61,5587.42 h60
  text "Top Layer - Bottom Layer" at 16111.95,5587.42 h60
  text "H" at 14260.99,5577.43 h44.28
  text "23" at 14568.36,5487.8 h60
  text "62.99mil (1.600mm)" at 14885.54,5487.8 h60
  text "PTH" at 15507.29,5487.8 h60
  text "Round" at 15751.61,5487.8 h60
  text "Top Layer - Bottom Layer" at 16111.95,5487.8 h60
  text "2" at 14568.36,5388.18 h60
  text "78.74mil (2.000mm)" at 14885.54,5388.18 h60
  text "PTH" at 15507.29,5388.18 h60
  text "Round" at 15751.61,5388.18 h60
  text "Top Layer - Bottom Layer" at 16111.95,5388.18 h60
  text "4" at 14568.36,5288.55 h60
  text "125.98mil (3.200mm)" at 14885.54,5288.55 h60
  text "PTH" at 15507.29,5288.55 h60
  text "Round" at 15751.61,5288.55 h60
  text "Top Layer - Bottom Layer" at 16111.95,5288.55 h60
  text "2" at 14568.36,5188.93 h60
  text "47.24mil (1.200mm)" at 14885.54,5188.93 h60
  text "PTH" at 15507.29,5188.93 h60
  text "Rectangle" at 15751.61,5188.93 h60
  text "Top Layer - Bottom Layer" at 16111.95,5188.93 h60
  text "202 Total" at 14568.36,5089.31 h60
  text "Slot definitions :" at 14282.61,5009.7 h60
  text "Routed Path Length" at 14725.92,5009.7 h60
  text "= Calculated from tool start centre position to tool end centre position." at 15258.25,5009.7 h60
  text "Hole Length" at 14725.92,4959.97 h60
  text "= Routed Path Length + Tool Size = Slot length as defined in the PCB layout" at 15058.45,4959.97 h60
  text ".Layer_Name" at 577,-937.23 h60
Mechanical 17:
  text ".Layer_Name" at 577,-937.23 h60
Mechanical 18:
  text ".Layer_Name" at 577,-937.23 h60
Mechanical 19:
  text ".Layer_Name" at 577,-937.23 h60

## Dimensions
0,-478.74 to 1000,-478.74 on M2 Board Dimensions
0,0 to 0,3937.01 on M2 Board Dimensions
0,0 to 7480.31,0 on M2 Board Dimensions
